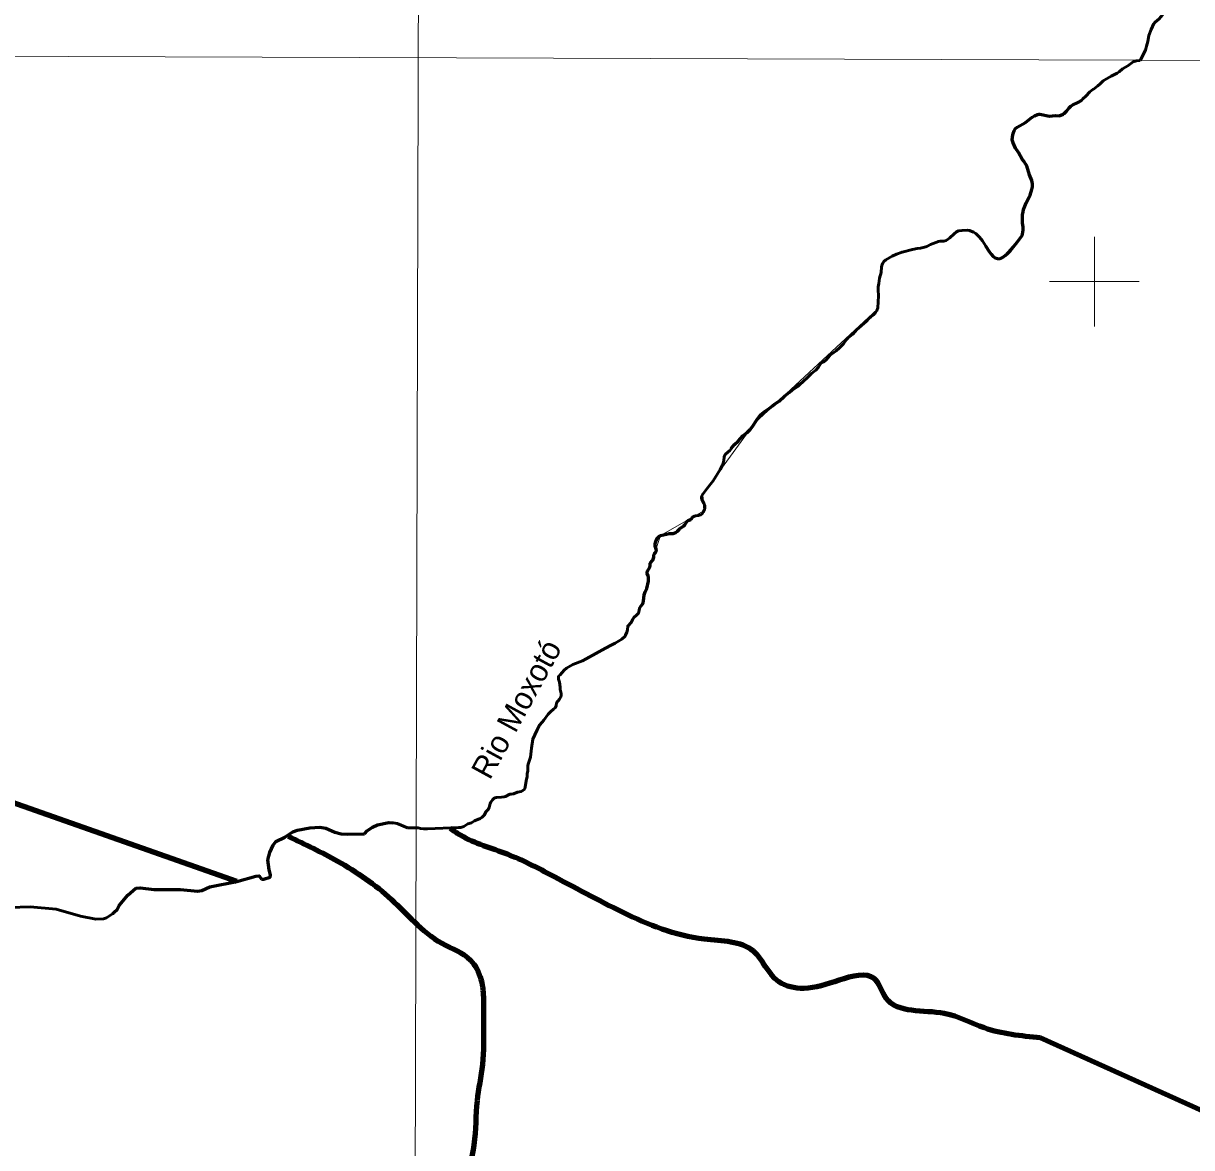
# Model space of a CAD drawing. Extents: x -1643653 to 4543381, y 1624270 to 13878484.
# Drawn here: x 601111 to 627167, y 8980683 to 9005760 of the extents above; entities that cross this region are included whole.
import ezdxf
from ezdxf.enums import TextEntityAlignment as Align

# ---------------------------------------------------------------- set-up
doc = ezdxf.new("R2010")
doc.units = 0
doc.header["$LTSCALE"] = 200
doc.linetypes.add('LONG_DASH_SHORT_DASH', pattern=[9.9, 6, -1.2, 1.5, -1.2])
for name, color, linetype, lineweight in [('1', 7, 'Continuous', 13), ('2', 7, 'Continuous', 13), ('24', 7, 'Continuous', 25), ('58', 7, 'Continuous', 13), ('60', 7, 'Continuous', 13), ('7', 7, 'LONG_DASH_SHORT_DASH', 60), ('9', 7, 'Continuous', 90)]:
    doc.layers.add(name, color=color, linetype=linetype, lineweight=lineweight)
doc.layers.add('49', color=7, linetype='Continuous')

msp = doc.modelspace()

# ---------------------------------------------------------------- linework, layer by layer
at = {"layer": '1'}
for points in [[(609971.9, 9023551.8), (609764.7, 8949706.7), (609734.2, 8939404.4)], [(565303.2, 9005146.6), (664889.8, 9004806.7), (719872.1, 9004543.9), (790635.8, 9004109)]]:
    msp.add_lwpolyline(points, dxfattribs=at)
at = {"layer": '2'}
for p, q in [((625000, 8999000), (625000, 9001000)), ((624000, 9000000), (626000, 9000000))]:
    msp.add_line(p, q, dxfattribs=at)
at = {"layer": '24', "lineweight": 53}
for points in [[(626161, 9005249.2), (626188.6, 9005351.8), (626211.6, 9005488.2), (626262, 9005622), (626290.8, 9005686), (626318.1, 9005740.6), (626357.2, 9005784), (626440.5, 9005861.4), (626481.1, 9005905.8), (626516.3, 9005951), (626547.5, 9005998.1), (626576.5, 9006046.2), (626606.6, 9006087.7), (626651.3, 9006133.9), (626697.2, 9006185.8), (626721.1, 9006227.2), (626725, 9006288.4)], [(626020.3, 9004931.6), (626138.4, 9005165.4), (626161, 9005249.2)], [(624968.7, 9004287.4), (625077.4, 9004367.4), (625125.3, 9004407.4), (625196.1, 9004475.4), (625232, 9004503.4), (625369.3, 9004583.4), (625507, 9004648.4), (625552.2, 9004680.4), (625627.3, 9004743.4), (625747.5, 9004813.4), (625804.8, 9004859.3), (625863.6, 9004898.3), (625936.5, 9004925.7), (626020.3, 9004931.6)], [(622356.1, 9001071.6), (622438.9, 9000988.6), (622501.2, 9000910.6), (622651.6, 9000673.6), (622694.8, 9000613.6), (622741.9, 9000562.6), (622781.6, 9000528.6), (622838, 9000513.6), (622887.5, 9000510.6), (622903.5, 9000513.6), (622951.5, 9000538.6), (623008.3, 9000580.6), (623061.1, 9000626.5), (623124.5, 9000694.5), (623279.2, 9000880.5), (623385, 9001031.5), (623398.2, 9001059.5), (623411.2, 9001147.5), (623406.1, 9001224.5), (623394.5, 9001300.5), (623396.9, 9001485.5), (623407.8, 9001557.5), (623420.7, 9001604.5), (623474.8, 9001753.5), (623546.5, 9001882.5), (623566.5, 9001928.5), (623606.4, 9002057.5), (623614.4, 9002114.5), (623615.2, 9002180.5), (623603.6, 9002252.5), (623548.9, 9002380.5), (623488.7, 9002579.5), (623465.3, 9002623.5), (623431.2, 9002675.5), (623387.3, 9002730.5), (623302, 9002882.5), (623235.1, 9002973.5), (623183.3, 9003094.5), (623167.7, 9003160.5), (623170, 9003229.5), (623186.6, 9003301.5), (623210, 9003362.5), (623241.9, 9003412.5), (623274.8, 9003442.5), (623462.1, 9003547.5), (623608.8, 9003667.5), (623666.2, 9003700.5), (623727.2, 9003726.5), (623755.6, 9003733.5), (623782.5, 9003731.5), (623993.5, 9003691.5), (624127.2, 9003701.5), (624209, 9003698.5), (624301.4, 9003736.4), (624324.7, 9003751.4), (624377.4, 9003798.4), (624433, 9003873.4), (624469.5, 9003912.4), (624514.8, 9003941.4), (624628.9, 9003992.4), (624709.5, 9004038.4), (624743.9, 9004077.4), (624810.6, 9004137.4), (624900.3, 9004230.4), (624968, 9004288.4)], [(620148.3, 8999353.7), (620168.6, 8999417.7), (620186.8, 8999678.7), (620178.1, 8999819.7), (620178.5, 8999880.7), (620194.3, 8999957.7), (620208.2, 9000078.7), (620242.8, 9000202.7), (620252.9, 9000329.7), (620263.2, 9000378.7), (620280.1, 9000412.7), (620305.3, 9000447.7), (620344.5, 9000485.7), (620432.6, 9000539.7), (620488.9, 9000569.7), (620581.6, 9000610.7), (620710.5, 9000657.7), (620939.4, 9000718.7), (621042.2, 9000740.6), (621118.4, 9000748.6), (621242.2, 9000776.6), (621275.5, 9000790.6), (621342.1, 9000826.6), (621518.2, 9000894.6), (621561.1, 9000901.6), (621637.2, 9000903.6), (621689.6, 9000916.6), (621716.6, 9000931.6), (621774.6, 9000977.6), (621867.2, 9001066.6), (621924.7, 9001110.6), (621967.5, 9001129.6), (622048.6, 9001140.6), (622160.3, 9001143.6), (622215.2, 9001136.6), (622300.1, 9001105.6), (622356.1, 9001071.6)], [(616275, 8994855), (616299.8, 8994916), (616306.6, 8994947), (616309.5, 8994997), (616289.9, 8995061), (616239.9, 8995143), (616235.6, 8995179), (616237.4, 8995206), (616262.8, 8995260), (616352.4, 8995378.9), (616439.6, 8995482.9), (616497.8, 8995558.9), (616654.6, 8995808.9), (616704.2, 8995904.9), (616721.4, 8995949.9), (616734.9, 8996009.9), (616742.4, 8996094.9), (616755.2, 8996130.9), (616770.5, 8996150.9), (616865.5, 8996231.9), (616968.5, 8996369.9), (617050.4, 8996439.9), (617160.7, 8996559.9), (617252.1, 8996633.9), (617320.9, 8996701.9), (617376, 8996767.9), (617466.2, 8996912.9), (617553.7, 8997026.9), (617627.5, 8997088.9), (617747.7, 8997167.8), (617821.7, 8997231.8), (617864.4, 8997264.8), (617970.3, 8997332.8), (618086, 8997441.8), (618201.6, 8997530.8), (618257.2, 8997582.8), (618380.8, 8997669.8), (618495.1, 8997763.8), (618608.2, 8997867.8), (618687.2, 8997947.8), (618784.2, 8998026.8), (618847.8, 8998091.8), (618880.8, 8998148.8), (618904.8, 8998177.8), (618927, 8998194.8), (618960.5, 8998211.8), (619017, 8998253.8), (619099.7, 8998350.8), (619132.8, 8998382.8), (619235.9, 8998457.8), (619310.3, 8998518.8), (619402.8, 8998610.8), (619472.9, 8998704.8), (619501.7, 8998736.7), (619608.1, 8998826.7), (619700.3, 8998928.7), (619746.9, 8998966.7), (619804.3, 8999021.7), (619907.6, 8999106.7), (619970.1, 8999177.7), (620010.3, 8999215.7), (620083.8, 8999267.7), (620109.1, 8999292.7), (620148.3, 8999353.7), (620148.3, 8999353.7)], [(615088.6, 8993660), (615092.1, 8993720), (615153, 8993790), (615174.6, 8993852), (615175.1, 8993904), (615179, 8993921), (615187.3, 8993934), (615211.5, 8993958), (615228.8, 8993992), (615227.7, 8994030), (615203.4, 8994096), (615199.3, 8994145), (615206.1, 8994178), (615239.1, 8994264), (615295.5, 8994325), (615320, 8994336), (615520.9, 8994382), (615601.5, 8994383), (615661.9, 8994403), (615699.6, 8994431), (615734.4, 8994474), (615755.4, 8994494), (615812.3, 8994527), (615840.8, 8994550), (615864.4, 8994578), (615900.1, 8994637), (615919.4, 8994659), (615934.8, 8994670), (615988.9, 8994692), (616008.8, 8994710), (616037.3, 8994745), (616076.4, 8994766), (616108.6, 8994778), (616169.1, 8994784), (616218.9, 8994795), (616250.2, 8994821), (616275, 8994855)], [(612374.7, 8989257.2), (612410.1, 8989349.2), (612422.8, 8989393.2), (612443.9, 8989595.2), (612472.1, 8989790.2), (612521.4, 8989889.2), (612567.7, 8990001.2), (612623.5, 8990108.2), (612679.4, 8990175.2), (612720.8, 8990217.2), (612815.3, 8990351.2), (612864.4, 8990407.2), (612937.9, 8990460.2), (612974.6, 8990496.2), (612997.1, 8990536.2), (613004.6, 8990605.2), (613071.9, 8990685.2), (613099.4, 8990741.2), (613104.8, 8990769.2), (613104.8, 8990813.2), (613086.3, 8990905.2), (613085.9, 8990954.2), (613066.1, 8991064.2), (613044.7, 8991133.2), (613043.4, 8991164.2), (613047.9, 8991196.2), (613081.7, 8991228.2), (613169.8, 8991332.2), (613227.7, 8991376.2), (613365.8, 8991458.1), (613579.6, 8991541.1), (613666.1, 8991582.1), (614090.8, 8991825.1), (614218.9, 8991891.1), (614310.9, 8991932.1), (614460.7, 8992023.1), (614532.5, 8992094.1), (614543.7, 8992113.1), (614569, 8992177.1), (614582, 8992234.1), (614589.2, 8992317.1), (614668.2, 8992394.1), (614704.5, 8992469.1), (614728, 8992505.1), (614788.8, 8992558.1), (614827.1, 8992602.1), (614841.2, 8992635.1), (614852.2, 8992705.1), (614861.2, 8992733.1), (614874, 8992755.1), (614920, 8992803.1), (614934.5, 8992832.1), (614943.5, 8992879.1), (614957.9, 8993016), (614981.1, 8993081), (615017.2, 8993154), (615053.5, 8993321), (615053.4, 8993409), (615046.2, 8993436), (615020.3, 8993489), (615020.7, 8993515), (615030.5, 8993541), (615082.9, 8993633), (615082.9, 8993633), (615088.6, 8993660)], [(610812.6, 8987820.3), (610868.6, 8987825.3), (610933, 8987849.3), (611023.7, 8987905.3), (611105.7, 8987931.3), (611174.3, 8987972.3), (611295.8, 8988024.3), (611334, 8988050.3), (611392.2, 8988106.3), (611428.2, 8988171.3), (611476.2, 8988225.3), (611496.6, 8988270.3), (611519.8, 8988356.3), (611535.1, 8988392.3), (611570.6, 8988443.3), (611611.3, 8988477.3), (611633.5, 8988486.3), (611663.2, 8988493.3), (611778.5, 8988500.3), (611831.3, 8988507.2), (611867.2, 8988517.2), (611960.5, 8988564.2), (611993.5, 8988570.2), (612040.4, 8988571.2), (612135.1, 8988609.2), (612211, 8988629.2), (612253, 8988646.2), (612280.4, 8988668.2), (612294.2, 8988690.2), (612304.8, 8988723.2), (612325, 8988861.2), (612344.1, 8988963.2), (612347.8, 8989019.2), (612358.9, 8989089.2), (612362.3, 8989210.2), (612374.7, 8989257.2)], [(608722.9, 8987680.8), (608777.9, 8987747.6), (608897.1, 8987833.6), (609009.5, 8987880.2), (609264.4, 8987935.4), (609356.3, 8987924.6)], [(609356.3, 8987924.6), (609448.1, 8987913.7), (609678.6, 8987816.5)], [(606420.8, 8986668), (606473.8, 8986668.1), (606613.3, 8986714.2), (606626.1, 8986769), (606594.2, 8986880), (606564.5, 8987100.6), (606609.1, 8987266.3), (606681.2, 8987431.8), (606741, 8987512.8), (606939.6, 8987610), (607118.9, 8987727.3), (607224.8, 8987767.6), (607501, 8987816.5), (607722.2, 8987831.4), (607811.1, 8987818.7)], [(607811.1, 8987818.7), (607857.5, 8987812), (608058.1, 8987723), (608202.2, 8987682.7), (608346.4, 8987672.1), (608722.9, 8987680.8)], [(609678.6, 8987816.5), (609919.3, 8987814.4), (609966, 8987801.4), (610032.6, 8987795.3), (610127.9, 8987794.3), (610812.6, 8987820.3)], [(604502.8, 8986438.7), (604614.5, 8986437.8), (604995.5, 8986406.1), (605088.3, 8986418.9), (605266.8, 8986501.7), (605873.8, 8986618.4), (606294.7, 8986737.4), (606369.1, 8986745.7), (606420.8, 8986668)], [(603138.8, 8985934.3), (603201.3, 8985995.2), (603246.4, 8986085.3), (603439.7, 8986316.8), (603622.3, 8986468.1), (603715.8, 8986478.2), (604022, 8986442.1), (604249.4, 8986440.5), (604502.8, 8986438.7)], [(600614.3, 8986048.6), (600805.6, 8986038.6), (601260, 8986057.6), (601842, 8986004.5), (602386.1, 8985845.2), (602725.9, 8985781.5), (602895.9, 8985787.9), (602963.8, 8985811.2), (603100.1, 8985896.5), (603138.8, 8985934.3)]]:
    msp.add_lwpolyline(points, dxfattribs=at)
at = {"layer": '58'}
for points in [[(626725, 9006288.4), (626721.1, 9006227.2), (626697.2, 9006185.8), (626651.3, 9006133.9), (626606.6, 9006087.7), (626576.5, 9006046.2), (626547.5, 9005998.1), (626516.3, 9005951), (626481.1, 9005905.8), (626440.5, 9005861.4), (626357.2, 9005784), (626318.1, 9005740.6), (626290.8, 9005686), (626262, 9005622), (626211.6, 9005488.2), (626188.6, 9005351.8), (626161, 9005249.2)], [(626161, 9005249.2), (626138.4, 9005165.4), (626020.3, 9004931.6), (625936.5, 9004925.7)], [(625936.5, 9004925.7), (625863.6, 9004898.3), (625804.8, 9004859.3), (625747.5, 9004813.4), (625627.3, 9004743.4), (625552.2, 9004680.4), (625507, 9004648.4), (625369.3, 9004583.4), (625232, 9004503.4), (625196.1, 9004475.4), (625125.3, 9004407.4), (625077.4, 9004367.4), (624968.7, 9004287.4), (624968, 9004288.4)], [(624968, 9004288.4), (624900.3, 9004230.4), (624810.6, 9004137.4), (624743.9, 9004077.4), (624712.1, 9004041.3), (624492.2, 9003926.9)], [(624492.2, 9003926.9), (624469.5, 9003912.4), (624433, 9003873.4), (624377.4, 9003798.4), (624324.7, 9003751.4), (624301.4, 9003736.4), (624209, 9003698.5), (624127.2, 9003701.5), (623993.5, 9003691.5), (623782.5, 9003731.5), (623755.6, 9003733.5), (623727.2, 9003726.5), (623666.2, 9003700.5), (623608.8, 9003667.5), (623462.1, 9003547.5), (623274.8, 9003442.5), (623241.9, 9003412.5), (623210, 9003362.5), (623186.6, 9003301.5), (623170, 9003229.5), (623167.7, 9003160.5), (623183.3, 9003094.5), (623235.1, 9002973.5), (623302, 9002882.5), (623387.3, 9002730.5), (623431.2, 9002675.5), (623465.3, 9002623.5), (623488.7, 9002579.5), (623548.9, 9002380.5), (623603.6, 9002252.5), (623615.2, 9002180.5)], [(623615.2, 9002180.5), (623614.4, 9002114.5), (623606.4, 9002057.5), (623566.5, 9001928.5), (623546.5, 9001882.5), (623474.8, 9001753.5), (623420.7, 9001604.5), (623407.8, 9001557.5), (623396.9, 9001485.5), (623394.5, 9001300.5), (623406.1, 9001224.5), (623411.2, 9001147.5), (623398.2, 9001059.5), (623391.6, 9001045.5)], [(622356.1, 9001071.6), (622300.1, 9001105.6), (622215.2, 9001136.6), (622160.3, 9001143.6), (622048.6, 9001140.6), (621967.5, 9001129.6), (621924.7, 9001110.6), (621867.2, 9001066.6), (621774.6, 9000977.6), (621716.6, 9000931.6), (621689.6, 9000916.6), (621637.2, 9000903.6), (621561.1, 9000901.6), (621518.2, 9000894.6), (621342.1, 9000826.6), (621275.5, 9000790.6), (621242.2, 9000776.6), (621118.4, 9000748.6), (621042.2, 9000740.6), (620939.4, 9000718.7), (620710.5, 9000657.7), (620581.6, 9000610.7), (620488.9, 9000569.7), (620432.6, 9000539.7), (620344.5, 9000485.7), (620305.3, 9000447.7), (620280.1, 9000412.7), (620263.2, 9000378.7), (620252.9, 9000329.7), (620242.8, 9000202.7), (620208.2, 9000078.7), (620194.3, 8999957.7), (620178.5, 8999880.7), (620178.1, 8999819.7), (620186.8, 8999678.7), (620168.6, 8999417.7), (620158.4, 8999385.7), (620158.4, 8999385.7)], [(622884.2, 9000510.8), (622838, 9000513.6), (622781.6, 9000528.6), (622741.9, 9000562.6), (622694.8, 9000613.6), (622651.6, 9000673.6), (622501.2, 9000910.6), (622438.9, 9000988.6), (622356.1, 9001071.6)], [(623391.6, 9001045.5), (622951.5, 9000538.6), (622884.2, 9000510.8)], [(620158.4, 8999385.7), (617421.1, 8996840.4), (616262.8, 8995260), (616287.4, 8994885.5), (615320, 8994336), (615082.9, 8993633), (615020.5, 8993502), (615053.5, 8993365), (615017.2, 8993154), (614957.9, 8993016), (614927.3, 8992817.6), (614861.2, 8992733.1), (614834.1, 8992618.6), (614728, 8992505.1), (614668.2, 8992394.1), (614589.2, 8992317.1), (614575.5, 8992205.6), (614496.6, 8992058.6), (613579.6, 8991541.1), (613227.7, 8991376.2), (613081.7, 8991228.2), (613044.1, 8991148.7), (613085.9, 8990954.2), (613085.7, 8990713.2), (613004.6, 8990605.2), (612985.8, 8990516.2), (612839.9, 8990379.2), (612623.5, 8990108.2), (612472.1, 8989790.2), (612280.4, 8988668.2), (611570.6, 8988443.3), (611476.2, 8988225.3), (611314.9, 8988037.3), (610868.6, 8987825.3), (609678.6, 8987816.5), (609356.3, 8987924.6), (609009.5, 8987880.2), (608837.5, 8987790.6), (608722.9, 8987680.8), (608130.2, 8987702.8), (607766.6, 8987825), (607501, 8987816.5), (607171.9, 8987747.4), (606939.6, 8987610), (606711.1, 8987472.3), (606564.5, 8987100.6), (606594.2, 8986880), (606613.3, 8986714.2), (606473.8, 8986668.1), (606331.9, 8986741.5), (605873.8, 8986618.4), (605266.8, 8986501.7), (605041.9, 8986412.5), (604614.5, 8986437.8), (604135.7, 8986441.3), (603622.3, 8986468.1), (603439.7, 8986316.8), (603246.4, 8986085.3), (603201.3, 8985995.2), (603104.5, 8985900.8), (602929.8, 8985799.6), (602725.9, 8985781.5), (602386.1, 8985845.2), (602114, 8985924.9), (601842, 8986004.5), (601551, 8986031.1), (600446.9, 8986057.4)]]:
    msp.add_lwpolyline(points, dxfattribs=at)
at = {"layer": '60', "lineweight": 25}
msp.add_spline([(814781, 9009175.5), (814787.2, 9009173.4), (814796.9, 9009173.4), (814799.4, 9009172.4), (814805.1, 9009174.5), (814805.6, 9009176.5), (814811.7, 9009179.5), (814811.7, 9009179.5), (814801.5, 9009181), (814790.7, 9009181.5), (814784.1, 9009183.1), (814777.4, 9009185.1), (814778.4, 9009175.5)], degree=3, dxfattribs=at)
at = {"layer": '7', "lineweight": 35}
msp.add_line((610685.7, 8987847), (610687.2, 8987846.5), dxfattribs=at)
at = {"layer": '7'}
msp.add_line((603104.5, 8985900.8), (603138.8, 8985934.3), dxfattribs=at)
for points in [[(622572.2, 9000798.7), (622651.6, 9000673.6), (622694.8, 9000613.6), (622741.9, 9000562.6), (622781.6, 9000528.6), (622838, 9000513.6), (622887.5, 9000510.6), (622903.5, 9000513.6), (622951.5, 9000538.6), (623008.3, 9000580.6), (623061.1, 9000626.5), (623124.5, 9000694.5), (623279.2, 9000880.5), (623385, 9001031.5), (623398.2, 9001059.5), (623411.2, 9001147.5), (623406.1, 9001224.5), (623394.5, 9001300.5), (623396.9, 9001485.5), (623407.8, 9001557.5), (623420.7, 9001604.5), (623474.8, 9001753.5), (623546.5, 9001882.5), (623566.5, 9001928.5), (623606.4, 9002057.5), (623614.4, 9002114.5), (623615.2, 9002180.5), (623603.6, 9002252.5), (623548.9, 9002380.5), (623488.7, 9002579.5), (623465.3, 9002623.5), (623431.2, 9002675.5), (623387.3, 9002730.5), (623302, 9002882.5), (623235.1, 9002973.5), (623183.3, 9003094.5), (623167.7, 9003160.5), (623170, 9003229.5), (623186.6, 9003301.5), (623210, 9003362.5), (623241.9, 9003412.5), (623274.8, 9003442.5), (623462.1, 9003547.5), (623608.8, 9003667.5), (623666.2, 9003700.5), (623727.2, 9003726.5), (623755.6, 9003733.5), (623782.5, 9003731.5), (623993.5, 9003691.5), (624127.2, 9003701.5), (624209, 9003698.5), (624301.4, 9003736.4), (624324.7, 9003751.4), (624377.4, 9003798.4), (624433, 9003873.4), (624469.5, 9003912.4), (624514.8, 9003941.4)], [(616899, 8996276.8), (616968.5, 8996369.9), (617050.4, 8996439.9), (617160.7, 8996559.9), (617252.1, 8996633.9), (617320.9, 8996701.9), (617376, 8996767.9), (617466.2, 8996912.9), (617553.7, 8997026.9), (617627.5, 8997088.9), (617747.7, 8997167.8), (617821.7, 8997231.8), (617864.4, 8997264.8), (617970.3, 8997332.8), (618086, 8997441.8), (618201.6, 8997530.8), (618257.2, 8997582.8), (618380.8, 8997669.8), (618437.7, 8997716.6)], [(615088.6, 8993660), (615092.1, 8993720), (615153, 8993790), (615174.6, 8993852), (615175.1, 8993904), (615179, 8993921), (615187.3, 8993934), (615211.5, 8993958), (615228.8, 8993992), (615227.7, 8994030), (615203.4, 8994096), (615199.3, 8994145), (615206.1, 8994178), (615239.1, 8994264), (615295.5, 8994325), (615320, 8994336), (615520.9, 8994382), (615601.5, 8994383), (615661.9, 8994403), (615699.6, 8994431), (615734.4, 8994474), (615755.4, 8994494), (615812.3, 8994527), (615840.8, 8994550), (615864.4, 8994578), (615900.1, 8994637), (615919.4, 8994659), (615934.8, 8994670), (615988.9, 8994692), (616008.8, 8994710), (616037.3, 8994745)], [(614923.2, 8992809.3), (614934.5, 8992832.1), (614943.5, 8992879.1), (614957.9, 8993016), (614981.1, 8993081), (615017.2, 8993154), (615053.5, 8993321), (615053.4, 8993409), (615046.2, 8993436), (615020.3, 8993489), (615020.7, 8993515), (615030.5, 8993541), (615082.9, 8993633), (615082.9, 8993633), (615088.6, 8993660)], [(608722.9, 8987680.8), (608777.9, 8987747.6), (608897.1, 8987833.6), (609009.5, 8987880.2), (609264.4, 8987935.4), (609347, 8987925.7)], [(606420.8, 8986668), (606473.8, 8986668.1), (606613.3, 8986714.2), (606626.1, 8986769), (606594.2, 8986880), (606564.5, 8987100.6), (606609.1, 8987266.3), (606681.2, 8987431.8), (606741, 8987512.8), (606939.6, 8987610), (607118.9, 8987727.3), (607224.8, 8987767.6), (607501, 8987816.5), (607722.2, 8987831.4), (607811.1, 8987818.7)], [(607811.1, 8987818.7), (607857.5, 8987812), (608058.1, 8987723), (608202.2, 8987682.7), (608346.4, 8987672.1), (608722.9, 8987680.8)], [(604502.8, 8986438.7), (604614.5, 8986437.8), (604995.5, 8986406.1), (605088.3, 8986418.9), (605266.8, 8986501.7), (605873.8, 8986618.4), (606294.7, 8986737.4), (606369.1, 8986745.7), (606420.8, 8986668)], [(603138.8, 8985934.3), (603201.3, 8985995.2), (603246.4, 8986085.3), (603439.7, 8986316.8), (603622.3, 8986468.1), (603715.8, 8986478.2), (604022, 8986442.1), (604249.4, 8986440.5), (604502.8, 8986438.7)]]:
    msp.add_lwpolyline(points, dxfattribs=at)
at = {"layer": '9'}
for points in [[(605873.8, 8986618.4), (590956.6, 8991866.7), (589163, 9005713.7)], [(637260.6, 8972975.8), (637390.8, 8977204.2), (635350.7, 8977923.9), (623791.9, 8983133)]]:
    msp.add_lwpolyline(points, dxfattribs=at)
for points in [[(607019.9, 8987628.8), (608117.9, 8987072.5), (609319, 8986220.3), (609831, 8985717.6), (610444.6, 8985240.9), (611083, 8984865.7), (611314.6, 8984437), (611367.4, 8984108.2), (611371.5, 8983424.7), (611351.3, 8982538.5), (611228.8, 8981727.5), (611158.3, 8980739.6), (611137.7, 8979929.4), (611547.1, 8979552.5), (611828.5, 8979301.3), (612340.6, 8978773.3), (612648.8, 8978294.5), (612832.8, 8977308.5), (612940.5, 8976321.9), (612949.5, 8974803), (612829.3, 8973612.2), (613105.4, 8971372.7), (613572.8, 8968712.3), (614200.8, 8967292.3), (614110, 8965907), (613645.9, 8964639.4)], [(623791.9, 8983133), (622543.6, 8983352), (621651, 8983674.8), (620351.1, 8984020), (620094.1, 8984448.6), (619305.4, 8984417.7), (618517.6, 8984234.9), (617956.8, 8984382.8), (617392.9, 8985062.3), (616297.1, 8985333.1), (614486.7, 8985927.8), (612853, 8986777), (611908.8, 8987226), (610862.9, 8987648.9), (610631.7, 8987802.8)]]:
    msp.add_spline(points, degree=3, dxfattribs=at)

# ---------------------------------------------------------------- texts
at = {"layer": '49'}
msp.add_text('Rio Moxotó', height=500, rotation=61.364, dxfattribs=at).set_placement((612325.1, 8990347.9), align=Align.CENTER)

doc.saveas('drawing.dxf')
